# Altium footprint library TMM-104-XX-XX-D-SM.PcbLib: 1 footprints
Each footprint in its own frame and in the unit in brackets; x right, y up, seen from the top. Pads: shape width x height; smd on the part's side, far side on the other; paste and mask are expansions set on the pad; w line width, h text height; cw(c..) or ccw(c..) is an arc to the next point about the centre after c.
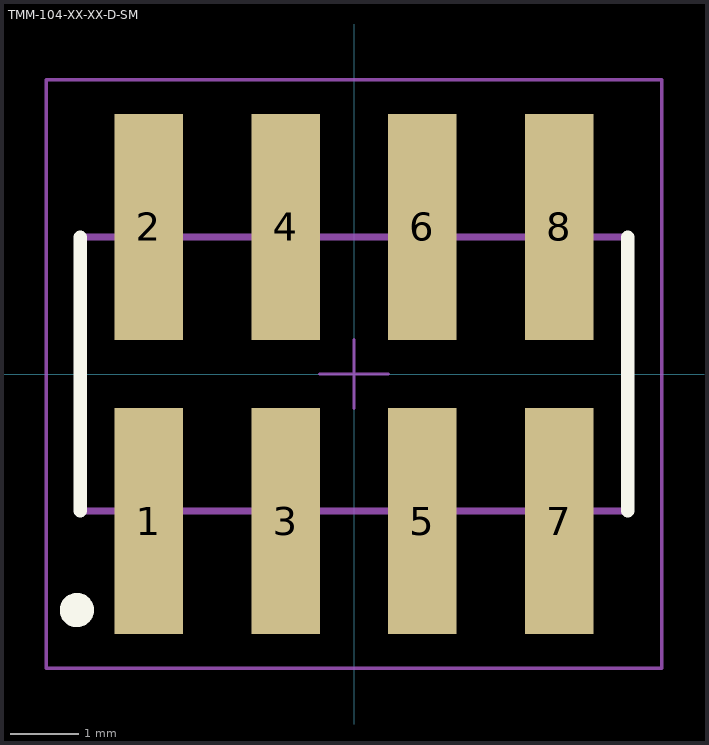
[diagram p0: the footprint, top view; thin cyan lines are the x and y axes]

## TMM-104-XX-XX-D-SM [mm] "2.00mm pitch, 40 pin, terminal strip; double row, SMT"
height 2.77
pads (8):
  rect 1x3.3 smd mask+0: 1(-3,-2.15) 2(-3,2.15) 3(-1,-2.15) 4(-1,2.15) 5(1,-2.15) 6(1,2.15) 7(3,-2.15) 8(3,2.15)
Top Overlay:
  circle w0.25: c-4.05,-3.45 r0.125
  lines w0.2: -4,-2 -4,2 ; 4,-2 4,2
Mechanical 12:
  lines w0.001: -4,-2 -4,2 4,2 4,-2 -4,-2
Mechanical 13:
  lines w0.1: -4,-2 -4,2 4,2 4,-2 -4,-2
  text ".Designator" at 0,-0.127 h1.52
Mechanical 15:
  lines w0.05: -0.5,0 0.5,0 ; 0,-0.5 0,0.5 ; -4.5,-4.3 -4.5,4.3 4.5,4.3 4.5,-4.3 -4.5,-4.3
